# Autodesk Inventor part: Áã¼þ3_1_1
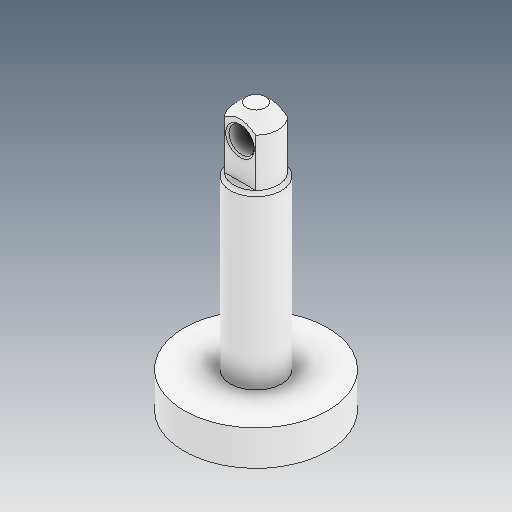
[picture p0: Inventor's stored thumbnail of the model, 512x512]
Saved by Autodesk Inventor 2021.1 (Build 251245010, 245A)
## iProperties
Created: 2021-05
Part Number: Áã¼þ3_1_1
Material: Ogólny
Document SubType Name: Modeling
Designer: user
Density: 1 g/cm^3
Appearance: Domyślna
Author: user
Revision Number: ÈÎºÎ
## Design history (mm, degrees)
feature "ÊäÈë1"
node "Bryła1"
